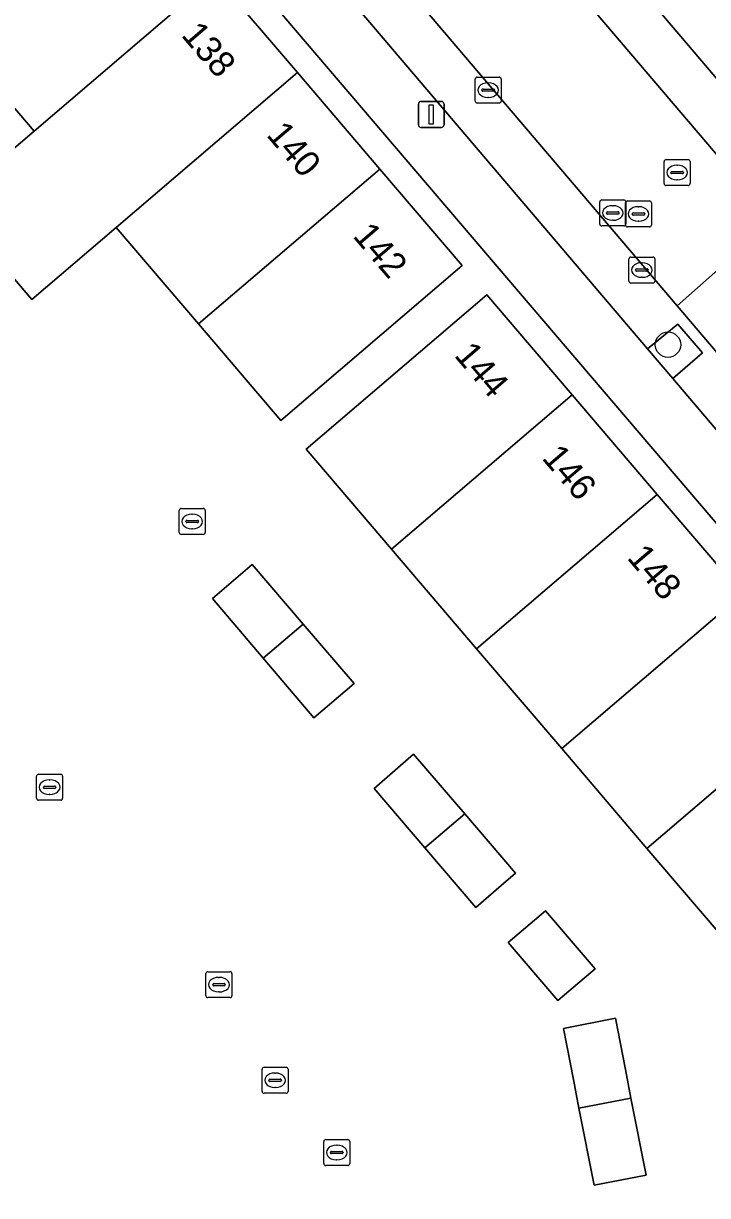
# Model space of a CAD drawing. Extents: x 160377 to 161131, y 383938 to 384853.
# Drawn here: x 160766.93 to 160793.29, y 384573.2 to 384618.33 of the extents above; entities that cross this region are included whole.
import ezdxf

# ---------------------------------------------------------------- set-up
doc = ezdxf.new("R2010")
doc.units = 0
for name, color, linetype in [('IMGEO_Boom', 7, 'Continuous'), ('IMGEO_Erf', 7, 'Continuous'), ('IMGEO_Groenvoorziening', 7, 'Continuous'), ('IMGEO_Kolk', 7, 'Continuous'), ('IMGEO_Lichtmast', 7, 'Continuous'), ('IMGEO_Pand', 7, 'Continuous'), ('IMGEO_Pand_nummerreeks', 7, 'Continuous'), ('IMGEO_Parkeervlak_open', 7, 'Continuous'), ('IMGEO_Rijbaan_lokaal_open', 7, 'Continuous'), ('IMGEO_Rioolput', 7, 'Continuous'), ('IMGEO_Voetpad_open', 7, 'Continuous')]:
    doc.layers.add(name, color=color, linetype=linetype)

msp = doc.modelspace()

# ---------------------------------------------------------------- linework, layer by layer
at = {"layer": 'IMGEO_Boom'}
msp.add_circle((160791.766, 384605.959), 0.489, dxfattribs=at)
at = {"layer": 'IMGEO_Erf'}
for points in [[(160814.707, 384533.039), (160805.221, 384581.626), (160804.227, 384586.696), (160801.827, 384589.484), (160785.555, 384608.533), (160784.593, 384609.659), (160759.221, 384639.361), (160756.612, 384642.415), (160753.096, 384646.531), (160752.089, 384647.71), (160738.611, 384663.488), (160738.585, 384663.466), (160731.208, 384657.183), (160728.177, 384654.568), (160723.454, 384650.553), (160720.379, 384647.933), (160715.683, 384643.941), (160712.616, 384641.352)], [(160796.655, 384572.409), (160795.673, 384577.454), (160794.768, 384582.1), (160794.236, 384582.722), (160790.955, 384586.564), (160787.673, 384590.406), (160784.391, 384594.248), (160781.11, 384598.09), (160777.828, 384601.932), (160784.785, 384607.875), (160788.067, 384604.033), (160791.349, 384600.191), (160794.631, 384596.35), (160797.913, 384592.508), (160801.195, 384588.667), (160803.34, 384586.156), (160804.705, 384579.154), (160805.677, 384574.166), (160806.66, 384569.122)]]:
    msp.add_lwpolyline(points, dxfattribs=at)
for points in [[(160757.82, 384625.32), (160754.648, 384629.033), (160751.476, 384632.745), (160754.966, 384635.727), (160758.456, 384638.708), (160761.628, 384634.996), (160764.8, 384631.283), (160767.972, 384627.571), (160771.144, 384623.858), (160774.316, 384620.146), (160777.488, 384616.433), (160780.66, 384612.721), (160783.832, 384609.008), (160776.853, 384603.045), (160773.681, 384606.758), (160770.509, 384610.47), (160767.258, 384607.692), (160764.086, 384611.405), (160767.337, 384614.183), (160764.164, 384617.895), (160760.992, 384621.608)], [(160774.213, 384596.183), (160775.74, 384597.491), (160777.708, 384595.196), (160779.667, 384592.911), (160778.123, 384591.589), (160776.168, 384593.886)], [(160780.441, 384588.875), (160781.96, 384590.192), (160783.933, 384587.893), (160785.888, 384585.616), (160785.342, 384585.144), (160784.355, 384584.29), (160782.398, 384586.582)], [(160787.041, 384584.167), (160788.954, 384581.927), (160787.525, 384580.706), (160785.611, 384582.946)], [(160788.327, 384576.563), (160788.122, 384577.668), (160787.735, 384579.636), (160789.741, 384580.031), (160790.129, 384578.057), (160790.334, 384576.952), (160790.93, 384573.986), (160788.923, 384573.597)]]:
    msp.add_lwpolyline(points, close=True, dxfattribs=at)
at = {"layer": 'IMGEO_Groenvoorziening'}
msp.add_lwpolyline([(160790.977, 384605.8), (160791.95, 384604.656), (160793.091, 384605.648), (160792.143, 384606.753)], close=True, dxfattribs=at)
at = {"layer": 'IMGEO_Kolk'}
for p, q in [((160784.336, 384615.333), (160784.336, 384616.185)), ((160784.411, 384616.259), (160785.263, 384616.259)), ((160784.824, 384616.039), (160784.849, 384616.039)), ((160785.337, 384616.185), (160785.337, 384615.333)), ((160784.595, 384615.753), (160784.595, 384615.765)), ((160785.033, 384615.716), (160784.635, 384615.716)), ((160784.638, 384615.802), (160785.036, 384615.802)), ((160785.079, 384615.765), (160785.079, 384615.753)), ((160785.263, 384615.259), (160784.411, 384615.259)), ((160784.847, 384615.479), (160784.822, 384615.479)), ((160790.258, 384608.407), (160790.258, 384609.259)), ((160790.333, 384609.333), (160791.185, 384609.333)), ((160791.259, 384609.259), (160791.259, 384608.407)), ((160790.517, 384608.827), (160790.517, 384608.839)), ((160790.955, 384608.79), (160790.557, 384608.79)), ((160790.56, 384608.876), (160790.958, 384608.876)), ((160790.746, 384609.113), (160790.771, 384609.113)), ((160791.001, 384608.839), (160791.001, 384608.827)), ((160791.185, 384608.333), (160790.333, 384608.333)), ((160790.769, 384608.553), (160790.744, 384608.553)), ((160772.932, 384598.726), (160772.932, 384599.578)), ((160773.007, 384599.652), (160773.859, 384599.652)), ((160773.42, 384599.432), (160773.445, 384599.432)), ((160773.933, 384599.578), (160773.933, 384598.726)), ((160773.191, 384599.146), (160773.191, 384599.158)), ((160773.629, 384599.109), (160773.231, 384599.109)), ((160773.234, 384599.195), (160773.632, 384599.195)), ((160773.443, 384598.872), (160773.418, 384598.872)), ((160773.675, 384599.158), (160773.675, 384599.146)), ((160773.859, 384598.652), (160773.007, 384598.652)), ((160767.513, 384589.421), (160768.365, 384589.421)), ((160767.438, 384588.495), (160767.438, 384589.347)), ((160767.697, 384588.915), (160767.697, 384588.927)), ((160767.74, 384588.964), (160768.138, 384588.964)), ((160767.926, 384589.201), (160767.951, 384589.201)), ((160768.181, 384588.927), (160768.181, 384588.915)), ((160768.439, 384589.347), (160768.439, 384588.495)), ((160768.135, 384588.878), (160767.737, 384588.878)), ((160767.949, 384588.641), (160767.924, 384588.641)), ((160768.365, 384588.421), (160767.513, 384588.421)), ((160773.963, 384580.894), (160773.963, 384581.746)), ((160774.038, 384581.82), (160774.89, 384581.82)), ((160774.964, 384581.746), (160774.964, 384580.894)), ((160774.222, 384581.314), (160774.222, 384581.326)), ((160774.66, 384581.277), (160774.262, 384581.277)), ((160774.265, 384581.363), (160774.663, 384581.363)), ((160774.451, 384581.6), (160774.476, 384581.6)), ((160774.706, 384581.326), (160774.706, 384581.314)), ((160774.89, 384580.82), (160774.038, 384580.82)), ((160774.474, 384581.04), (160774.449, 384581.04)), ((160778.501, 384574.432), (160778.501, 384575.284)), ((160778.576, 384575.358), (160779.428, 384575.358)), ((160778.989, 384575.138), (160779.014, 384575.138)), ((160779.502, 384575.284), (160779.502, 384574.432)), ((160778.76, 384574.852), (160778.76, 384574.864)), ((160779.198, 384574.815), (160778.8, 384574.815)), ((160778.803, 384574.901), (160779.201, 384574.901)), ((160779.012, 384574.578), (160778.987, 384574.578)), ((160779.244, 384574.864), (160779.244, 384574.852)), ((160779.428, 384574.358), (160778.576, 384574.358))]:
    msp.add_line(p, q, dxfattribs=at)
for points in [[(160784.336, 384615.333), (160784.336, 384616.185)], [(160784.411, 384616.259), (160785.263, 384616.259)], [(160785.337, 384616.185), (160785.337, 384615.333)], [(160785.263, 384615.259), (160784.411, 384615.259)], [(160790.258, 384608.407), (160790.258, 384609.259)], [(160790.333, 384609.333), (160791.185, 384609.333)], [(160791.259, 384609.259), (160791.259, 384608.407)], [(160791.185, 384608.333), (160790.333, 384608.333)], [(160772.932, 384598.726), (160772.932, 384599.578)], [(160773.007, 384599.652), (160773.859, 384599.652)], [(160773.933, 384599.578), (160773.933, 384598.726)], [(160773.859, 384598.652), (160773.007, 384598.652)], [(160767.513, 384589.421), (160768.365, 384589.421)], [(160767.438, 384588.495), (160767.438, 384589.347)], [(160768.439, 384589.347), (160768.439, 384588.495)], [(160768.365, 384588.421), (160767.513, 384588.421)], [(160773.963, 384580.894), (160773.963, 384581.746)], [(160774.038, 384581.82), (160774.89, 384581.82)], [(160774.964, 384581.746), (160774.964, 384580.894)], [(160774.89, 384580.82), (160774.038, 384580.82)], [(160778.501, 384574.432), (160778.501, 384575.284)], [(160778.576, 384575.358), (160779.428, 384575.358)], [(160779.502, 384575.284), (160779.502, 384574.432)], [(160779.428, 384574.358), (160778.576, 384574.358)]]:
    msp.add_lwpolyline(points, dxfattribs=at)
for centre, radius, start, end in [((160784.413, 384616.183), 0.0765, 91.552, 178.448), ((160784.413, 384616.183), 0.0765, 91.552, 178.448), ((160785.261, 384616.183), 0.0765, 1.552, 88.448), ((160785.261, 384616.183), 0.0765, 1.552, 88.448), ((160784.635, 384615.762), 0.0403, 85.8775, 175.7526), ((160784.632, 384615.752), 0.0366, 178.938, 274.7102), ((160785.036, 384615.759), 0.043, 264.8664, 352.4533), ((160785.04, 384615.764), 0.0386, 1.7309, 96.639), ((160784.413, 384615.335), 0.0765, 181.552, 268.448), ((160784.413, 384615.335), 0.0765, 181.552, 268.448), ((160785.261, 384615.335), 0.0765, 271.552, 358.448), ((160785.261, 384615.335), 0.0765, 271.552, 358.448), ((160790.335, 384609.257), 0.0765, 91.552, 178.448), ((160790.335, 384609.257), 0.0765, 91.552, 178.448), ((160791.183, 384609.257), 0.0765, 1.552, 88.448), ((160791.183, 384609.257), 0.0765, 1.552, 88.448), ((160790.557, 384608.836), 0.0403, 85.8775, 175.7526), ((160790.554, 384608.826), 0.0366, 178.938, 274.7102), ((160790.958, 384608.833), 0.043, 264.8664, 352.4533), ((160790.962, 384608.838), 0.0386, 1.7309, 96.639), ((160790.335, 384608.409), 0.0765, 181.552, 268.448), ((160790.335, 384608.409), 0.0765, 181.552, 268.448), ((160791.183, 384608.409), 0.0765, 271.552, 358.448), ((160791.183, 384608.409), 0.0765, 271.552, 358.448), ((160773.009, 384599.576), 0.0765, 91.552, 178.448), ((160773.009, 384599.576), 0.0765, 91.552, 178.448), ((160773.857, 384599.576), 0.0765, 1.552, 88.448), ((160773.857, 384599.576), 0.0765, 1.552, 88.448), ((160773.231, 384599.155), 0.0403, 85.8775, 175.7526), ((160773.228, 384599.145), 0.0366, 178.938, 274.7102), ((160773.632, 384599.152), 0.043, 264.8664, 352.4533), ((160773.636, 384599.157), 0.0386, 1.7309, 96.639), ((160773.009, 384598.728), 0.0765, 181.552, 268.448), ((160773.009, 384598.728), 0.0765, 181.552, 268.448), ((160773.857, 384598.728), 0.0765, 271.552, 358.448), ((160773.857, 384598.728), 0.0765, 271.552, 358.448), ((160767.515, 384589.345), 0.0765, 91.552, 178.448), ((160767.515, 384589.345), 0.0765, 91.552, 178.448), ((160768.363, 384589.345), 0.0765, 1.552, 88.448), ((160768.363, 384589.345), 0.0765, 1.552, 88.448), ((160767.737, 384588.924), 0.0403, 85.8775, 175.7526), ((160767.734, 384588.914), 0.0366, 178.938, 274.7102), ((160768.138, 384588.921), 0.043, 264.8664, 352.4533), ((160768.142, 384588.926), 0.0386, 1.7309, 96.639), ((160767.515, 384588.497), 0.0765, 181.552, 268.448), ((160767.515, 384588.497), 0.0765, 181.552, 268.448), ((160768.363, 384588.497), 0.0765, 271.552, 358.448), ((160768.363, 384588.497), 0.0765, 271.552, 358.448), ((160774.04, 384581.744), 0.0765, 91.552, 178.448), ((160774.04, 384581.744), 0.0765, 91.552, 178.448), ((160774.888, 384581.744), 0.0765, 1.552, 88.448), ((160774.888, 384581.744), 0.0765, 1.552, 88.448), ((160774.262, 384581.323), 0.0403, 85.8775, 175.7526), ((160774.259, 384581.313), 0.0366, 178.938, 274.7102), ((160774.663, 384581.32), 0.043, 264.8664, 352.4533), ((160774.667, 384581.325), 0.0386, 1.7309, 96.639), ((160774.04, 384580.896), 0.0765, 181.552, 268.448), ((160774.04, 384580.896), 0.0765, 181.552, 268.448), ((160774.888, 384580.896), 0.0765, 271.552, 358.448), ((160774.888, 384580.896), 0.0765, 271.552, 358.448), ((160778.578, 384575.282), 0.0765, 91.552, 178.448), ((160778.578, 384575.282), 0.0765, 91.552, 178.448), ((160779.426, 384575.282), 0.0765, 1.552, 88.448), ((160779.426, 384575.282), 0.0765, 1.552, 88.448), ((160778.8, 384574.861), 0.0403, 85.8775, 175.7526), ((160778.797, 384574.851), 0.0366, 178.938, 274.7102), ((160779.201, 384574.858), 0.043, 264.8664, 352.4533), ((160779.205, 384574.863), 0.0386, 1.7309, 96.639), ((160778.578, 384574.434), 0.0765, 181.552, 268.448), ((160778.578, 384574.434), 0.0765, 181.552, 268.448), ((160779.426, 384574.434), 0.0765, 271.552, 358.448), ((160779.426, 384574.434), 0.0765, 271.552, 358.448)]:
    msp.add_arc(centre, radius, start, end, dxfattribs=at)
for centre, major_axis, ratio, start_param, end_param in [((160784.823, 384615.759), (-0.387, 0.002), 0.722429, 4.712389, 7.853982), ((160784.848, 384615.759), (-0.39, 0.002), 0.717154, 1.570796, 4.712389), ((160790.745, 384608.833), (-0.387, 0.002), 0.722429, 4.712389, 7.853982), ((160790.77, 384608.833), (-0.39, 0.002), 0.717154, 1.570796, 4.712389), ((160773.419, 384599.152), (-0.387, 0.002), 0.722429, 4.712389, 7.853982), ((160773.444, 384599.152), (-0.39, 0.002), 0.717154, 1.570796, 4.712389), ((160767.925, 384588.921), (-0.387, 0.002), 0.722429, 4.712389, 7.853982), ((160767.95, 384588.921), (-0.39, 0.002), 0.717154, 1.570796, 4.712389), ((160774.45, 384581.32), (-0.387, 0.002), 0.722429, 4.712389, 7.853982), ((160774.475, 384581.32), (-0.39, 0.002), 0.717154, 1.570796, 4.712389), ((160778.988, 384574.858), (-0.387, 0.002), 0.722429, 4.712389, 7.853982), ((160779.013, 384574.858), (-0.39, 0.002), 0.717154, 1.570796, 4.712389)]:
    msp.add_ellipse(centre, major_axis=major_axis, ratio=ratio, start_param=start_param, end_param=end_param, dxfattribs=at)
at = {"layer": 'IMGEO_Lichtmast'}
for p, q in [((160782.147, 384614.423), (160782.147, 384615.223)), ((160782.147, 384615.223), (160782.147, 384614.423)), ((160782.247, 384615.323), (160783.037, 384615.323)), ((160783.037, 384615.323), (160782.247, 384615.323)), ((160783.137, 384615.223), (160783.137, 384614.423)), ((160783.137, 384614.423), (160783.137, 384615.223)), ((160783.037, 384614.323), (160782.247, 384614.323)), ((160782.247, 384614.323), (160783.037, 384614.323))]:
    msp.add_line(p, q, dxfattribs=at)
msp.add_lwpolyline([(160782.567, 384615.198), (160782.717, 384615.198), (160782.717, 384614.448), (160782.567, 384614.448), (160782.567, 384615.198)], dxfattribs=at)
for centre, start, end in [((160782.247, 384615.223), 90, 180), ((160782.247, 384615.223), 90, 180), ((160783.037, 384615.223), 0, 90), ((160783.037, 384615.223), 360, 90), ((160782.247, 384614.423), 180, 270), ((160782.247, 384614.423), 180, 270), ((160783.037, 384614.423), 270, 0), ((160783.037, 384614.423), 270, 0)]:
    msp.add_arc(centre, 0.1, start, end, dxfattribs=at)
at = {"layer": 'IMGEO_Pand'}
for points in [[(160774.316, 384620.146), (160771.144, 384623.858), (160764.164, 384617.895), (160767.337, 384614.183)], [(160777.488, 384616.433), (160774.316, 384620.146), (160767.337, 384614.183), (160764.086, 384611.405), (160767.258, 384607.692), (160770.509, 384610.47)], [(160780.66, 384612.721), (160777.488, 384616.433), (160770.509, 384610.47), (160773.681, 384606.758)], [(160783.832, 384609.008), (160780.66, 384612.721), (160773.681, 384606.758), (160776.853, 384603.045)], [(160788.067, 384604.033), (160784.785, 384607.875), (160777.828, 384601.932), (160781.11, 384598.09)], [(160791.349, 384600.191), (160788.067, 384604.033), (160781.11, 384598.09), (160784.391, 384594.248)], [(160794.631, 384596.35), (160791.349, 384600.191), (160784.391, 384594.248), (160787.673, 384590.406)], [(160774.213, 384596.183), (160776.168, 384593.886), (160777.708, 384595.196), (160775.74, 384597.491)], [(160797.913, 384592.508), (160794.631, 384596.35), (160787.673, 384590.406), (160790.955, 384586.564)], [(160777.708, 384595.196), (160776.168, 384593.886), (160778.123, 384591.589), (160779.667, 384592.911)], [(160801.195, 384588.667), (160797.913, 384592.508), (160790.955, 384586.564), (160794.236, 384582.722)], [(160780.441, 384588.875), (160782.398, 384586.582), (160783.933, 384587.893), (160781.96, 384590.192)], [(160783.933, 384587.893), (160782.398, 384586.582), (160784.355, 384584.29), (160785.342, 384585.144), (160785.888, 384585.616)], [(160787.041, 384584.167), (160785.611, 384582.946), (160787.525, 384580.706), (160788.954, 384581.927)], [(160789.741, 384580.031), (160787.735, 384579.636), (160788.122, 384577.668), (160788.327, 384576.563), (160790.334, 384576.952), (160790.129, 384578.057)], [(160790.334, 384576.952), (160788.327, 384576.563), (160788.923, 384573.597), (160790.93, 384573.986)]]:
    msp.add_lwpolyline(points, close=True, dxfattribs=at)
at = {"layer": 'IMGEO_Parkeervlak_open'}
for points in [[(160749.03, 384665.578), (160795.82, 384610.729), (160804.54, 384600.506), (160810.989, 384592.947)], [(160812.448, 384594.132), (160752.443, 384664.534)], [(160806.649, 384590.394), (160805.962, 384591.216), (160805.813, 384591.386), (160800.781, 384597.292), (160792.118, 384607.459), (160763.891, 384640.584)], [(160764.518, 384636.892), (160774.881, 384624.714), (160776.07, 384625.726), (160777.163, 384624.482), (160775.954, 384623.453), (160790.977, 384605.8), (160792.143, 384606.753), (160793.091, 384605.648), (160791.95, 384604.656), (160798.979, 384596.397), (160800.006, 384597.358), (160801.093, 384596.179), (160799.972, 384595.231), (160803.397, 384591.205)]]:
    msp.add_lwpolyline(points, dxfattribs=at)
at = {"layer": 'IMGEO_Rijbaan_lokaal_open'}
for points in [[(160749.03, 384665.578), (160748.341, 384666.363), (160748.316, 384666.394), (160744.525, 384663.186), (160745.67, 384661.89), (160758.652, 384646.689), (160763.891, 384640.584), (160792.118, 384607.459), (160795.82, 384610.729)], [(160795.82, 384610.729), (160792.118, 384607.459), (160800.781, 384597.292), (160804.54, 384600.506)]]:
    msp.add_lwpolyline(points, close=True, dxfattribs=at)
at = {"layer": 'IMGEO_Rioolput'}
for p, q in [((160791.617, 384612.16), (160791.617, 384613.012)), ((160791.692, 384613.086), (160792.544, 384613.086)), ((160792.105, 384612.866), (160792.13, 384612.866)), ((160792.618, 384613.012), (160792.618, 384612.16)), ((160791.876, 384612.58), (160791.876, 384612.592)), ((160792.314, 384612.543), (160791.916, 384612.543)), ((160791.919, 384612.629), (160792.317, 384612.629)), ((160792.36, 384612.592), (160792.36, 384612.58)), ((160792.544, 384612.086), (160791.692, 384612.086)), ((160792.128, 384612.306), (160792.103, 384612.306)), ((160789.213, 384611.529), (160790.065, 384611.529)), ((160790.203, 384611.491), (160791.055, 384611.491)), ((160789.138, 384610.603), (160789.138, 384611.455)), ((160789.397, 384611.023), (160789.397, 384611.035)), ((160789.44, 384611.072), (160789.838, 384611.072)), ((160789.626, 384611.309), (160789.651, 384611.309)), ((160789.881, 384611.035), (160789.881, 384611.023)), ((160790.128, 384610.565), (160790.128, 384611.417)), ((160790.139, 384611.455), (160790.139, 384610.603)), ((160790.43, 384611.034), (160790.828, 384611.034)), ((160790.616, 384611.271), (160790.641, 384611.271)), ((160791.129, 384611.417), (160791.129, 384610.565)), ((160789.835, 384610.986), (160789.437, 384610.986)), ((160789.649, 384610.749), (160789.624, 384610.749)), ((160790.387, 384610.985), (160790.387, 384610.997)), ((160790.825, 384610.948), (160790.427, 384610.948)), ((160790.639, 384610.711), (160790.614, 384610.711)), ((160790.871, 384610.997), (160790.871, 384610.985)), ((160790.065, 384610.529), (160789.213, 384610.529)), ((160791.055, 384610.491), (160790.203, 384610.491)), ((160776.202, 384578.138), (160777.054, 384578.138)), ((160776.127, 384577.212), (160776.127, 384578.064)), ((160776.386, 384577.632), (160776.386, 384577.644)), ((160776.429, 384577.681), (160776.827, 384577.681)), ((160776.615, 384577.918), (160776.64, 384577.918)), ((160776.87, 384577.644), (160776.87, 384577.632)), ((160777.128, 384578.064), (160777.128, 384577.212)), ((160776.824, 384577.595), (160776.426, 384577.595)), ((160776.638, 384577.358), (160776.613, 384577.358)), ((160777.054, 384577.138), (160776.202, 384577.138))]:
    msp.add_line(p, q, dxfattribs=at)
for points in [[(160791.617, 384612.16), (160791.617, 384613.012)], [(160791.692, 384613.086), (160792.544, 384613.086)], [(160792.618, 384613.012), (160792.618, 384612.16)], [(160792.544, 384612.086), (160791.692, 384612.086)], [(160789.213, 384611.529), (160790.065, 384611.529)], [(160790.203, 384611.491), (160791.055, 384611.491)], [(160789.138, 384610.603), (160789.138, 384611.455)], [(160790.128, 384610.565), (160790.128, 384611.417)], [(160790.139, 384611.455), (160790.139, 384610.603)], [(160791.129, 384611.417), (160791.129, 384610.565)], [(160790.065, 384610.529), (160789.213, 384610.529)], [(160791.055, 384610.491), (160790.203, 384610.491)], [(160776.202, 384578.138), (160777.054, 384578.138)], [(160776.127, 384577.212), (160776.127, 384578.064)], [(160777.128, 384578.064), (160777.128, 384577.212)], [(160777.054, 384577.138), (160776.202, 384577.138)]]:
    msp.add_lwpolyline(points, dxfattribs=at)
for centre, radius, start, end in [((160791.694, 384613.01), 0.0765, 91.552, 178.448), ((160791.694, 384613.01), 0.0765, 91.552, 178.448), ((160792.542, 384613.01), 0.0765, 1.552, 88.448), ((160792.542, 384613.01), 0.0765, 1.552, 88.448), ((160791.916, 384612.589), 0.0403, 85.8775, 175.7526), ((160791.913, 384612.579), 0.0366, 178.938, 274.7102), ((160792.317, 384612.586), 0.043, 264.8664, 352.4533), ((160792.321, 384612.591), 0.0386, 1.7309, 96.639), ((160791.694, 384612.162), 0.0765, 181.552, 268.448), ((160791.694, 384612.162), 0.0765, 181.552, 268.448), ((160792.542, 384612.162), 0.0765, 271.552, 358.448), ((160792.542, 384612.162), 0.0765, 271.552, 358.448), ((160789.215, 384611.453), 0.0765, 91.552, 178.448), ((160789.215, 384611.453), 0.0765, 91.552, 178.448), ((160790.063, 384611.453), 0.0765, 1.552, 88.448), ((160790.063, 384611.453), 0.0765, 1.552, 88.448), ((160790.205, 384611.415), 0.0765, 91.552, 178.448), ((160790.205, 384611.415), 0.0765, 91.552, 178.448), ((160791.053, 384611.415), 0.0765, 1.552, 88.448), ((160791.053, 384611.415), 0.0765, 1.552, 88.448), ((160789.437, 384611.032), 0.0403, 85.8775, 175.7526), ((160789.434, 384611.022), 0.0366, 178.938, 274.7102), ((160789.838, 384611.029), 0.043, 264.8664, 352.4533), ((160789.842, 384611.034), 0.0386, 1.7309, 96.639), ((160790.427, 384610.994), 0.0403, 85.8775, 175.7526), ((160790.832, 384610.996), 0.0386, 1.7309, 96.639), ((160789.215, 384610.605), 0.0765, 181.552, 268.448), ((160789.215, 384610.605), 0.0765, 181.552, 268.448), ((160790.063, 384610.605), 0.0765, 271.552, 358.448), ((160790.063, 384610.605), 0.0765, 271.552, 358.448), ((160790.205, 384610.567), 0.0765, 181.552, 268.448), ((160790.205, 384610.567), 0.0765, 181.552, 268.448), ((160790.424, 384610.984), 0.0366, 178.938, 274.7102), ((160790.828, 384610.991), 0.043, 264.8664, 352.4533), ((160791.053, 384610.567), 0.0765, 271.552, 358.448), ((160791.053, 384610.567), 0.0765, 271.552, 358.448), ((160776.204, 384578.062), 0.0765, 91.552, 178.448), ((160776.204, 384578.062), 0.0765, 91.552, 178.448), ((160777.052, 384578.062), 0.0765, 1.552, 88.448), ((160777.052, 384578.062), 0.0765, 1.552, 88.448), ((160776.426, 384577.641), 0.0403, 85.8775, 175.7526), ((160776.423, 384577.631), 0.0366, 178.938, 274.7102), ((160776.827, 384577.638), 0.043, 264.8664, 352.4533), ((160776.831, 384577.643), 0.0386, 1.7309, 96.639), ((160776.204, 384577.214), 0.0765, 181.552, 268.448), ((160776.204, 384577.214), 0.0765, 181.552, 268.448), ((160777.052, 384577.214), 0.0765, 271.552, 358.448), ((160777.052, 384577.214), 0.0765, 271.552, 358.448)]:
    msp.add_arc(centre, radius, start, end, dxfattribs=at)
for centre, major_axis, ratio, start_param, end_param in [((160792.104, 384612.586), (-0.387, 0.002), 0.722429, 4.712389, 7.853982), ((160792.129, 384612.586), (-0.39, 0.002), 0.717154, 1.570796, 4.712389), ((160789.625, 384611.029), (-0.387, 0.002), 0.722429, 4.712389, 7.853982), ((160789.65, 384611.029), (-0.39, 0.002), 0.717154, 1.570796, 4.712389), ((160790.615, 384610.991), (-0.387, 0.002), 0.722429, 4.712389, 7.853982), ((160790.64, 384610.991), (-0.39, 0.002), 0.717154, 1.570796, 4.712389), ((160776.614, 384577.638), (-0.387, 0.002), 0.722429, 4.712389, 7.853982), ((160776.639, 384577.638), (-0.39, 0.002), 0.717154, 1.570796, 4.712389)]:
    msp.add_ellipse(centre, major_axis=major_axis, ratio=ratio, start_param=start_param, end_param=end_param, dxfattribs=at)
at = {"layer": 'IMGEO_Voetpad_open'}
for points in [[(160745.948, 384658.713), (160745.656, 384658.636), (160741.646, 384663.363), (160743.2, 384664.676), (160741.8, 384666.319), (160738.611, 384663.488), (160752.089, 384647.71), (160753.096, 384646.531), (160756.612, 384642.415), (160759.221, 384639.361), (160784.593, 384609.659), (160785.555, 384608.533), (160801.827, 384589.484), (160804.227, 384586.696), (160805.221, 384581.626), (160814.707, 384533.039), (160818.393, 384535.428), (160818.27, 384536.051), (160818.259, 384536.105), (160816.219, 384535.713), (160815.52, 384539.282), (160815.7, 384539.483)], [(160752.443, 384664.534), (160812.448, 384594.132)], [(160803.397, 384591.205), (160799.972, 384595.231), (160798.979, 384596.397), (160791.95, 384604.656), (160790.977, 384605.8), (160775.954, 384623.453), (160774.881, 384624.714), (160764.518, 384636.892)]]:
    msp.add_lwpolyline(points, dxfattribs=at)

# ---------------------------------------------------------------- texts
at = {"layer": 'IMGEO_Pand_nummerreeks'}
for s, rotation, p in [('138', 310.5136, (160772.98, 384617.861)), ('140', 310.5136, (160776.261, 384614.021)), ('142', 310.5136, (160779.586, 384610.13)), ('144', 310.5079, (160783.497, 384605.534)), ('146', 310.5079, (160786.873, 384601.583)), ('148', 310.5079, (160790.153, 384597.743))]:
    msp.add_text(s, height=1, rotation=rotation, dxfattribs=at).set_placement(p)

doc.saveas('drawing.dxf')
